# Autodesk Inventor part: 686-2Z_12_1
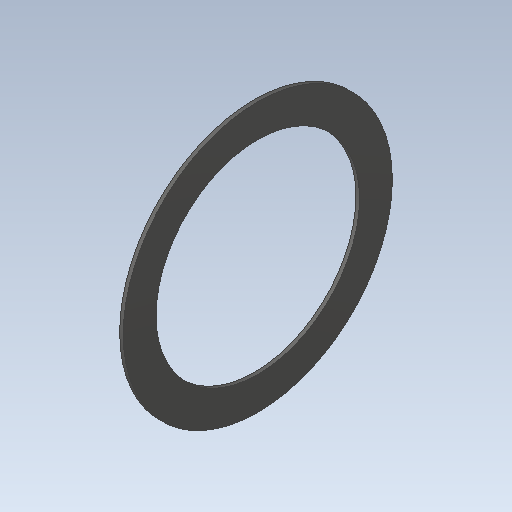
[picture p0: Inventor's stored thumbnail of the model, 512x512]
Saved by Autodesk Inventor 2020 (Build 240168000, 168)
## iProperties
Created: 2017-11
Part Number: 686-2Z_12_1
Material: Ogólny
Document SubType Name: Modeling
Designer: Tomasz
Density: 1 g/cm^3
Appearance: Domyślna
Sending System: SolidWorks 2017
Last Author: Tomasz
Last Saved: 2017-11-19
Source: 686-2Z_12_1
Author: Tomasz
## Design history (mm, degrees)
feature "Imported1"
node "Bryła1"
